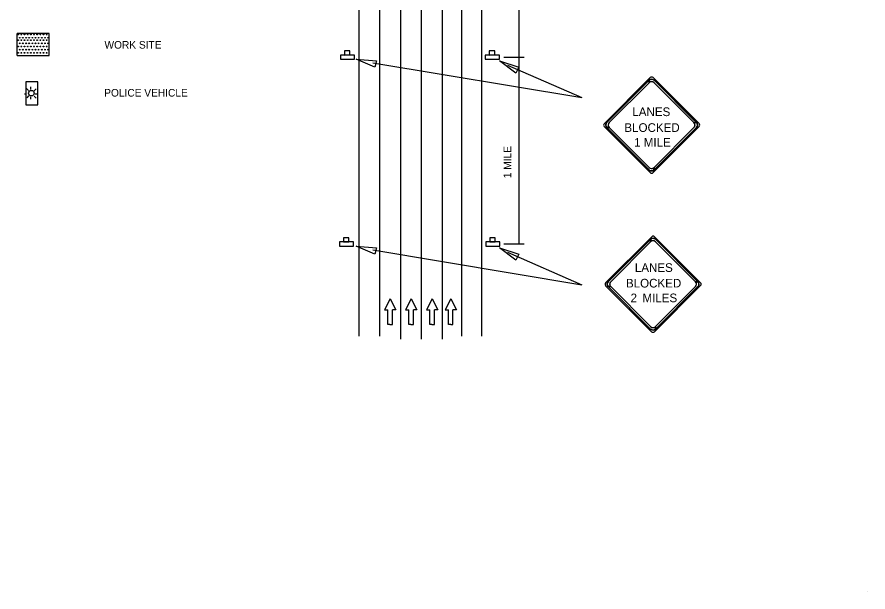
# Model space of a CAD drawing. Extents: x 1536.8 to 1543.6, y 1529.9 to 1539.9.
# Drawn here: x 1536.9 to 1543.62, y 1529.94 to 1534.47 of the extents above; entities that cross this region are included whole.
import ezdxf

# ---------------------------------------------------------------- set-up
doc = ezdxf.new("R2010")
doc.units = 0
for name, color, linetype in [('DETL-DIMS', 7, 'Continuous'), ('DETL-LINE', 7, 'Continuous'), ('DETL-NOTE', 7, 'Continuous'), ('TTLB-TEXT', 7, 'Continuous'), ('USER-BORD', 7, 'Continuous')]:
    doc.layers.add(name, color=color, linetype=linetype)

# ---------------------------------------------------------------- blocks, each defined once
blk = doc.blocks.new('DIR2')
at = {"layer": 'USER-BORD'}
for p, q in [((0, 0.0012), (-0.0342, -0.0477)), ((0, 0.0012), (0.0342, -0.0477)), ((-0.0342, -0.0477), (-0.0132, -0.0477)), ((-0.0132, -0.1133), (-0.0132, -0.0477)), ((0.0342, -0.0477), (0.0132, -0.0477)), ((0.0132, -0.1133), (0.0132, -0.0477)), ((-0.0011, -0.1133), (-0.0132, -0.1133)), ((-0.0011, -0.1133), (0.0011, -0.1133)), ((0.0011, -0.1133), (0.0132, -0.1133))]:
    blk.add_line(p, q, dxfattribs=at)
blk = doc.blocks.new('SIGN13')
at = {"layer": 'USER-BORD'}
for points in [[(-0.0314, 0.0182), (-0.0314, 0), (0.032, 0), (0.032, 0.0182)], [(-0.0134, 0.0182), (0.011, 0.0189), (0.011, 0.0371), (-0.0134, 0.0371)]]:
    blk.add_lwpolyline(points, close=True, dxfattribs=at)

msp = doc.modelspace()

# ---------------------------------------------------------------- linework, layer by layer
at = {"layer": 'DETL-DIMS'}
for p, q in [((1540.8663, 1532.683), (1540.8663, 1537.8458)), ((1540.7471, 1534.1567), (1540.9067, 1534.1567)), ((1539.7115, 1534.1114), (1541.3619, 1533.8372)), ((1540.7751, 1534.0935), (1541.3619, 1533.8372)), ((1540.7471, 1532.683), (1540.9067, 1532.683)), ((1539.7115, 1532.6354), (1541.3619, 1532.3611)), ((1540.7751, 1532.6175), (1541.3619, 1532.3611))]:
    msp.add_line(p, q, dxfattribs=at)
for points in [[(1539.7401, 1534.1285), (1539.7274, 1534.0775), (1539.5808, 1534.141)], [(1540.8647, 1534.0778), (1540.8401, 1534.0314), (1540.7131, 1534.1283)], [(1539.7401, 1532.6525), (1539.7274, 1532.6015), (1539.5808, 1532.665)], [(1540.8647, 1532.6019), (1540.8401, 1532.5554), (1540.7131, 1532.6523)]]:
    msp.add_lwpolyline(points, close=True, dxfattribs=at)
at = {"layer": 'DETL-LINE'}
for p, q in [((1539.6016, 1537.8471), (1539.6016, 1531.9568)), ((1539.7657, 1537.8471), (1539.7657, 1531.9568)), ((1540.4133, 1537.8471), (1540.4133, 1531.9568)), ((1540.5695, 1537.8471), (1540.5695, 1531.9568)), ((1539.9299, 1537.8213), (1539.9299, 1531.9311)), ((1540.0941, 1537.8213), (1540.0941, 1531.9311)), ((1540.2582, 1537.8213), (1540.2582, 1531.9311)), ((1537.1566, 1534.3438), (1536.9026, 1534.3438)), ((1537.1566, 1534.3438), (1536.9026, 1534.3438)), ((1537.1566, 1534.3438), (1536.9026, 1534.3438)), ((1537.1566, 1534.3438), (1536.9026, 1534.3438)), ((1536.9026, 1534.1697), (1536.9026, 1534.3437)), ((1536.9026, 1534.1698), (1536.9026, 1534.3437)), ((1536.9112, 1534.3349), (1536.9112, 1534.3349)), ((1536.912, 1534.3349), (1536.912, 1534.3349)), ((1536.9368, 1534.3349), (1536.9368, 1534.3349)), ((1536.9368, 1534.3349), (1536.9368, 1534.3349)), ((1536.9616, 1534.3349), (1536.9616, 1534.3349)), ((1536.9624, 1534.3349), (1536.9624, 1534.3349)), ((1536.9864, 1534.3349), (1536.9864, 1534.3349)), ((1536.9872, 1534.3349), (1536.9872, 1534.3349)), ((1537.0112, 1534.3349), (1537.0112, 1534.3349)), ((1537.012, 1534.3349), (1537.012, 1534.3349)), ((1537.0368, 1534.3349), (1537.0368, 1534.3349)), ((1537.0368, 1534.3349), (1537.0368, 1534.3349)), ((1537.0616, 1534.3349), (1537.0616, 1534.3349)), ((1537.0616, 1534.3349), (1537.0616, 1534.3349)), ((1537.0864, 1534.3349), (1537.0864, 1534.3349)), ((1537.0872, 1534.3349), (1537.0872, 1534.3349)), ((1537.1112, 1534.3349), (1537.1112, 1534.3349)), ((1537.112, 1534.3349), (1537.112, 1534.3349)), ((1537.1368, 1534.3349), (1537.1368, 1534.3349)), ((1537.1368, 1534.3349), (1537.1368, 1534.3349)), ((1537.1566, 1534.1698), (1537.1566, 1534.3438)), ((1537.1566, 1534.1698), (1537.1566, 1534.3438)), ((1537.1566, 1534.1698), (1537.1566, 1534.3438)), ((1537.1566, 1534.1698), (1537.1566, 1534.3438)), ((1536.9112, 1534.2911), (1536.9112, 1534.2911)), ((1536.912, 1534.2911), (1536.912, 1534.2911)), ((1536.924, 1534.3101), (1536.924, 1534.3101)), ((1536.924, 1534.3101), (1536.924, 1534.3101)), ((1536.924, 1534.2655), (1536.924, 1534.2655)), ((1536.9368, 1534.2911), (1536.9368, 1534.2911)), ((1536.9368, 1534.2911), (1536.9368, 1534.2911)), ((1536.9488, 1534.3101), (1536.9488, 1534.3101)), ((1536.9488, 1534.3101), (1536.9488, 1534.3101)), ((1536.9488, 1534.2655), (1536.9488, 1534.2655)), ((1536.9616, 1534.2911), (1536.9616, 1534.2911)), ((1536.9624, 1534.2911), (1536.9624, 1534.2911)), ((1536.9744, 1534.3101), (1536.9744, 1534.3101)), ((1536.9744, 1534.3101), (1536.9744, 1534.3101)), ((1536.9744, 1534.2655), (1536.9744, 1534.2655)), ((1536.9864, 1534.2911), (1536.9864, 1534.2911)), ((1536.9872, 1534.2911), (1536.9872, 1534.2911)), ((1536.9992, 1534.3101), (1536.9992, 1534.3101)), ((1536.9992, 1534.3101), (1536.9992, 1534.3101)), ((1536.9992, 1534.2655), (1536.9992, 1534.2655)), ((1537.0112, 1534.2911), (1537.0112, 1534.2911)), ((1537.012, 1534.2911), (1537.012, 1534.2911)), ((1537.024, 1534.3101), (1537.024, 1534.3101)), ((1537.024, 1534.3101), (1537.024, 1534.3101)), ((1537.024, 1534.2655), (1537.024, 1534.2655)), ((1537.0368, 1534.2911), (1537.0368, 1534.2911)), ((1537.0368, 1534.2911), (1537.0368, 1534.2911)), ((1537.0488, 1534.3101), (1537.0488, 1534.3101)), ((1537.0488, 1534.3101), (1537.0488, 1534.3101)), ((1537.0488, 1534.2655), (1537.0488, 1534.2655)), ((1537.0616, 1534.2911), (1537.0616, 1534.2911)), ((1537.0616, 1534.2911), (1537.0616, 1534.2911)), ((1537.0736, 1534.3101), (1537.0736, 1534.3101)), ((1537.0736, 1534.3101), (1537.0736, 1534.3101)), ((1537.0736, 1534.2655), (1537.0736, 1534.2655)), ((1537.0864, 1534.2911), (1537.0864, 1534.2911)), ((1537.0872, 1534.2911), (1537.0872, 1534.2911)), ((1537.0992, 1534.3101), (1537.0992, 1534.3101)), ((1537.0992, 1534.3101), (1537.0992, 1534.3101)), ((1537.0992, 1534.2655), (1537.0992, 1534.2655)), ((1537.1112, 1534.2911), (1537.1112, 1534.2911)), ((1537.112, 1534.2911), (1537.112, 1534.2911)), ((1537.124, 1534.3101), (1537.124, 1534.3101)), ((1537.124, 1534.3101), (1537.124, 1534.3101)), ((1537.124, 1534.2655), (1537.124, 1534.2655)), ((1537.1368, 1534.2911), (1537.1368, 1534.2911)), ((1537.1368, 1534.2911), (1537.1368, 1534.2911)), ((1537.1488, 1534.3101), (1537.1488, 1534.3101)), ((1537.1488, 1534.3101), (1537.1488, 1534.3101)), ((1537.1488, 1534.2655), (1537.1488, 1534.2655)), ((1536.9112, 1534.2407), (1536.9112, 1534.2407)), ((1536.912, 1534.2407), (1536.912, 1534.2407)), ((1536.924, 1534.2159), (1536.924, 1534.2159)), ((1536.924, 1534.2159), (1536.924, 1534.2159)), ((1536.9368, 1534.2407), (1536.9368, 1534.2407)), ((1536.9368, 1534.2407), (1536.9368, 1534.2407)), ((1536.9488, 1534.2159), (1536.9488, 1534.2159)), ((1536.9488, 1534.2159), (1536.9488, 1534.2159)), ((1536.9616, 1534.2407), (1536.9616, 1534.2407)), ((1536.9624, 1534.2407), (1536.9624, 1534.2407)), ((1536.9744, 1534.2159), (1536.9744, 1534.2159)), ((1536.9744, 1534.2159), (1536.9744, 1534.2159)), ((1536.9864, 1534.2407), (1536.9864, 1534.2407)), ((1536.9872, 1534.2407), (1536.9872, 1534.2407)), ((1536.9992, 1534.2159), (1536.9992, 1534.2159)), ((1536.9992, 1534.2159), (1536.9992, 1534.2159)), ((1537.0112, 1534.2407), (1537.0112, 1534.2407)), ((1537.012, 1534.2407), (1537.012, 1534.2407)), ((1537.024, 1534.2159), (1537.024, 1534.2159)), ((1537.024, 1534.2159), (1537.024, 1534.2159)), ((1537.0368, 1534.2407), (1537.0368, 1534.2407)), ((1537.0368, 1534.2407), (1537.0368, 1534.2407)), ((1537.0488, 1534.2159), (1537.0488, 1534.2159)), ((1537.0488, 1534.2159), (1537.0488, 1534.2159)), ((1537.0616, 1534.2407), (1537.0616, 1534.2407)), ((1537.0616, 1534.2407), (1537.0616, 1534.2407)), ((1537.0736, 1534.2159), (1537.0736, 1534.2159)), ((1537.0736, 1534.2159), (1537.0736, 1534.2159)), ((1537.0864, 1534.2407), (1537.0864, 1534.2407)), ((1537.0872, 1534.2407), (1537.0872, 1534.2407)), ((1537.0992, 1534.2159), (1537.0992, 1534.2159)), ((1537.0992, 1534.2159), (1537.0992, 1534.2159)), ((1537.1112, 1534.2407), (1537.1112, 1534.2407)), ((1537.112, 1534.2407), (1537.112, 1534.2407)), ((1537.124, 1534.2159), (1537.124, 1534.2159)), ((1537.124, 1534.2159), (1537.124, 1534.2159)), ((1537.1368, 1534.2407), (1537.1368, 1534.2407)), ((1537.1368, 1534.2407), (1537.1368, 1534.2407)), ((1537.1488, 1534.2159), (1537.1488, 1534.2159)), ((1537.1488, 1534.2159), (1537.1488, 1534.2159)), ((1536.9026, 1534.1697), (1537.1566, 1534.1697)), ((1536.9112, 1534.1915), (1536.9112, 1534.1915)), ((1536.912, 1534.1915), (1536.912, 1534.1915)), ((1536.9368, 1534.1915), (1536.9368, 1534.1915)), ((1536.9368, 1534.1915), (1536.9368, 1534.1915)), ((1536.9616, 1534.1915), (1536.9616, 1534.1915)), ((1536.9624, 1534.1915), (1536.9624, 1534.1915)), ((1536.9864, 1534.1915), (1536.9864, 1534.1915)), ((1536.9872, 1534.1915), (1536.9872, 1534.1915)), ((1537.0112, 1534.1915), (1537.0112, 1534.1915)), ((1537.012, 1534.1915), (1537.012, 1534.1915)), ((1537.0368, 1534.1915), (1537.0368, 1534.1915)), ((1537.0368, 1534.1915), (1537.0368, 1534.1915)), ((1537.0616, 1534.1915), (1537.0616, 1534.1915)), ((1537.0616, 1534.1915), (1537.0616, 1534.1915)), ((1537.0864, 1534.1915), (1537.0864, 1534.1915)), ((1537.0872, 1534.1915), (1537.0872, 1534.1915)), ((1537.1112, 1534.1915), (1537.1112, 1534.1915)), ((1537.112, 1534.1915), (1537.112, 1534.1915)), ((1537.1368, 1534.1915), (1537.1368, 1534.1915)), ((1537.1368, 1534.1915), (1537.1368, 1534.1915)), ((1541.9027, 1533.9954), (1541.5386, 1533.6314)), ((1542.2884, 1533.6322), (1541.9252, 1533.9954)), ((1536.971, 1533.9614), (1536.971, 1533.781)), ((1537.0662, 1533.9614), (1536.971, 1533.9614)), ((1537.0662, 1533.781), (1537.0662, 1533.9614)), ((1541.5591, 1533.6399), (1541.8938, 1533.9747)), ((1541.8938, 1533.9554), (1541.5783, 1533.64)), ((1542.2478, 1533.6399), (1541.9324, 1533.9554)), ((1541.9325, 1533.9747), (1542.2671, 1533.6399)), ((1536.9608, 1533.8676), (1536.9764, 1533.8676)), ((1536.9937, 1533.8927), (1536.9786, 1533.9087)), ((1537.0115, 1533.9028), (1537.0115, 1533.9224)), ((1537.0378, 1533.8916), (1537.0528, 1533.9062)), ((1537.0466, 1533.8676), (1537.0622, 1533.8676)), ((1536.9817, 1533.8361), (1536.9968, 1533.8506)), ((1537.0115, 1533.8247), (1537.0115, 1533.8442)), ((1537.0532, 1533.8336), (1537.0383, 1533.8496)), ((1536.971, 1533.781), (1537.0662, 1533.781)), ((1541.5386, 1533.6089), (1541.9018, 1533.2457)), ((1541.8938, 1533.2666), (1541.5591, 1533.6013)), ((1541.5783, 1533.6013), (1541.8938, 1533.2859)), ((1541.9244, 1533.2457), (1542.2884, 1533.6097)), ((1542.2671, 1533.6013), (1541.9325, 1533.2666)), ((1541.9325, 1533.2859), (1542.2478, 1533.6013)), ((1541.9142, 1532.7404), (1541.5502, 1532.3764)), ((1541.5707, 1532.3849), (1541.9054, 1532.7197)), ((1542.3, 1532.3772), (1541.9368, 1532.7404)), ((1541.944, 1532.7197), (1542.2787, 1532.3849)), ((1541.9054, 1532.7004), (1541.5899, 1532.385)), ((1542.2594, 1532.3849), (1541.944, 1532.7004)), ((1541.5502, 1532.3539), (1541.9134, 1531.9907)), ((1541.9054, 1532.0116), (1541.5707, 1532.3463)), ((1541.5899, 1532.3463), (1541.9054, 1532.0309)), ((1541.9359, 1531.9907), (1542.3, 1532.3547)), ((1542.2787, 1532.3463), (1541.944, 1532.0116)), ((1541.944, 1532.0309), (1542.2594, 1532.3463))]:
    msp.add_line(p, q, dxfattribs=at)
for points in [[(1539.9299, 1534.4713), (1539.9299, 1534.3713)], [(1540.0941, 1534.4713), (1540.0941, 1534.3713)], [(1540.2582, 1534.4713), (1540.2582, 1534.3713)], [(1539.9299, 1534.0713), (1539.9299, 1533.9713)], [(1540.0941, 1534.0713), (1540.0941, 1533.9713)], [(1540.2582, 1534.0713), (1540.2582, 1533.9713)], [(1539.9299, 1533.6713), (1539.9299, 1533.5713)], [(1540.0941, 1533.6713), (1540.0941, 1533.5713)], [(1540.2582, 1533.6713), (1540.2582, 1533.5713)], [(1539.9299, 1533.2713), (1539.9299, 1533.1713)], [(1540.0941, 1533.2713), (1540.0941, 1533.1713)], [(1540.2582, 1533.2713), (1540.2582, 1533.1713)], [(1539.9299, 1532.8713), (1539.9299, 1532.7713)], [(1540.0941, 1532.8713), (1540.0941, 1532.7713)], [(1540.2582, 1532.8713), (1540.2582, 1532.7713)], [(1539.9299, 1532.4713), (1539.9299, 1532.3713)], [(1540.0941, 1532.4713), (1540.0941, 1532.3713)], [(1540.2582, 1532.4713), (1540.2582, 1532.3713)], [(1539.9299, 1532.0713), (1539.9299, 1531.9713)], [(1540.0941, 1532.0713), (1540.0941, 1531.9713)], [(1540.2582, 1532.0713), (1540.2582, 1531.9713)]]:
    msp.add_lwpolyline(points, dxfattribs=at)
for points in [[(1541.5591, 1533.6399), (1541.8842, 1533.965), (1541.895, 1533.9758), (1541.8938, 1533.9554), (1541.5783, 1533.64), (1541.5733, 1533.6332), (1541.5704, 1533.6231), (1541.5712, 1533.6138), (1541.5738, 1533.6074), (1541.5783, 1533.6013), (1541.5591, 1533.6013), (1541.5536, 1533.6092), (1541.5511, 1533.6196), (1541.5519, 1533.6274), (1541.5543, 1533.6336)], [(1541.9324, 1533.9746), (1542.2574, 1533.6496), (1542.2682, 1533.6387), (1542.2478, 1533.6399), (1541.9325, 1533.9554), (1541.9256, 1533.9604), (1541.9155, 1533.9632), (1541.9062, 1533.9625), (1541.8999, 1533.96), (1541.8938, 1533.9554), (1541.8938, 1533.9746), (1541.9016, 1533.9801), (1541.9121, 1533.9826), (1541.9198, 1533.9818), (1541.9261, 1533.9794)], [(1541.8938, 1533.2666), (1541.5687, 1533.5917), (1541.5579, 1533.6025), (1541.5783, 1533.6013), (1541.8937, 1533.2859), (1541.9006, 1533.2809), (1541.9107, 1533.278), (1541.9199, 1533.2788), (1541.9263, 1533.2813), (1541.9324, 1533.2859), (1541.9324, 1533.2666), (1541.9245, 1533.2611), (1541.9141, 1533.2586), (1541.9063, 1533.2595), (1541.9, 1533.2619)], [(1542.2671, 1533.6013), (1541.942, 1533.2763), (1541.9311, 1533.2655), (1541.9324, 1533.2859), (1542.2478, 1533.6013), (1542.2528, 1533.6082), (1542.2557, 1533.6182), (1542.2549, 1533.6275), (1542.2524, 1533.6339), (1542.2478, 1533.6399), (1542.2671, 1533.6399), (1542.2726, 1533.6321), (1542.2751, 1533.6216), (1542.2743, 1533.6139), (1542.2718, 1533.6076)], [(1541.5707, 1532.3849), (1541.8957, 1532.71), (1541.9066, 1532.7208), (1541.9054, 1532.7004), (1541.5899, 1532.385), (1541.5849, 1532.3781), (1541.582, 1532.3681), (1541.5828, 1532.3588), (1541.5853, 1532.3524), (1541.5899, 1532.3463), (1541.5707, 1532.3463), (1541.5651, 1532.3542), (1541.5626, 1532.3646), (1541.5635, 1532.3724), (1541.5659, 1532.3786)], [(1541.944, 1532.7196), (1542.269, 1532.3945), (1542.2798, 1532.3837), (1542.2594, 1532.3849), (1541.944, 1532.7004), (1541.9371, 1532.7054), (1541.9271, 1532.7082), (1541.9178, 1532.7075), (1541.9114, 1532.705), (1541.9054, 1532.7004), (1541.9054, 1532.7196), (1541.9132, 1532.7251), (1541.9237, 1532.7276), (1541.9314, 1532.7268), (1541.9377, 1532.7243)], [(1542.2786, 1532.3463), (1541.9535, 1532.0213), (1541.9427, 1532.0105), (1541.944, 1532.0309), (1542.2594, 1532.3463), (1542.2644, 1532.3531), (1542.2673, 1532.3632), (1542.2665, 1532.3725), (1542.264, 1532.3788), (1542.2594, 1532.3849), (1542.2786, 1532.3849), (1542.2841, 1532.3771), (1542.2867, 1532.3666), (1542.2858, 1532.3589), (1542.2834, 1532.3526)], [(1541.9054, 1532.0116), (1541.5803, 1532.3367), (1541.5695, 1532.3475), (1541.5899, 1532.3463), (1541.9053, 1532.0309), (1541.9121, 1532.0259), (1541.9222, 1532.023), (1541.9315, 1532.0238), (1541.9379, 1532.0263), (1541.944, 1532.0309), (1541.944, 1532.0116), (1541.9361, 1532.0061), (1541.9256, 1532.0036), (1541.9179, 1532.0044), (1541.9116, 1532.0069)]]:
    msp.add_lwpolyline(points, close=True, dxfattribs=at)
for centre, radius in [((1536.9119, 1534.3348), 0.00291), ((1536.9367, 1534.3348), 0.00291), ((1536.9623, 1534.3348), 0.00291), ((1536.9871, 1534.3348), 0.00291), ((1537.0119, 1534.3348), 0.00291), ((1537.0367, 1534.3348), 0.00291), ((1537.0615, 1534.3348), 0.00291), ((1537.0871, 1534.3348), 0.00291), ((1537.1119, 1534.3348), 0.00291), ((1537.1367, 1534.3348), 0.00291), ((1536.9119, 1534.2911), 0.00291), ((1536.9239, 1534.31), 0.00291), ((1536.9239, 1534.2655), 0.00291), ((1536.9367, 1534.2911), 0.00291), ((1536.9487, 1534.31), 0.00291), ((1536.9487, 1534.2655), 0.00291), ((1536.9623, 1534.2911), 0.00291), ((1536.9743, 1534.31), 0.00291), ((1536.9743, 1534.2655), 0.00291), ((1536.9871, 1534.2911), 0.00291), ((1536.9991, 1534.31), 0.00291), ((1536.9991, 1534.2655), 0.00291), ((1537.0119, 1534.2911), 0.00291), ((1537.0239, 1534.31), 0.00291), ((1537.0239, 1534.2655), 0.00291), ((1537.0367, 1534.2911), 0.00291), ((1537.0487, 1534.31), 0.00291), ((1537.0487, 1534.2655), 0.00291), ((1537.0615, 1534.2911), 0.00291), ((1537.0735, 1534.31), 0.00291), ((1537.0735, 1534.2655), 0.00291), ((1537.0871, 1534.2911), 0.00291), ((1537.0991, 1534.31), 0.00291), ((1537.0991, 1534.2655), 0.00291), ((1537.1119, 1534.2911), 0.00291), ((1537.1239, 1534.31), 0.00291), ((1537.1239, 1534.2655), 0.00291), ((1537.1367, 1534.2911), 0.00291), ((1537.1487, 1534.31), 0.00291), ((1537.1487, 1534.2655), 0.00291), ((1536.9119, 1534.2407), 0.00291), ((1536.9119, 1534.1914), 0.00291), ((1536.9239, 1534.2159), 0.00291), ((1536.9367, 1534.2407), 0.00291), ((1536.9367, 1534.1914), 0.00291), ((1536.9487, 1534.2159), 0.00291), ((1536.9623, 1534.2407), 0.00291), ((1536.9623, 1534.1914), 0.00291), ((1536.9743, 1534.2159), 0.00291), ((1536.9871, 1534.2407), 0.00291), ((1536.9871, 1534.1914), 0.00291), ((1536.9991, 1534.2159), 0.00291), ((1537.0119, 1534.2407), 0.00291), ((1537.0119, 1534.1914), 0.00291), ((1537.0239, 1534.2159), 0.00291), ((1537.0367, 1534.2407), 0.00291), ((1537.0367, 1534.1914), 0.00291), ((1537.0487, 1534.2159), 0.00291), ((1537.0615, 1534.2407), 0.00291), ((1537.0615, 1534.1914), 0.00291), ((1537.0735, 1534.2159), 0.00291), ((1537.0871, 1534.2407), 0.00291), ((1537.0871, 1534.1914), 0.00291), ((1537.0991, 1534.2159), 0.00291), ((1537.1119, 1534.2407), 0.00291), ((1537.1119, 1534.1914), 0.00291), ((1537.1239, 1534.2159), 0.00291), ((1537.1367, 1534.2407), 0.00291), ((1537.1367, 1534.1914), 0.00291), ((1537.1487, 1534.2159), 0.00291), ((1537.0163, 1533.8724), 0.0221)]:
    msp.add_circle(centre, radius, dxfattribs=at)
for centre, radius, start, end in [((1541.9139, 1533.9842), 0.0159, 45, 135), ((1541.9131, 1533.9554), 0.0273, 45, 135), ((1541.9131, 1533.9361), 0.0273, 45, 135), ((1541.5499, 1533.6202), 0.0159, 135, 225), ((1541.5784, 1533.6206), 0.0273, 135, 225), ((1541.5977, 1533.6207), 0.0273, 135, 225), ((1542.2285, 1533.6206), 0.0273, 315, 45), ((1542.2479, 1533.6206), 0.0273, 315, 45), ((1542.2771, 1533.621), 0.0159, 315, 45), ((1541.9131, 1533.3052), 0.0273, 225, 315), ((1541.9131, 1533.2859), 0.0273, 225, 315), ((1541.9131, 1533.257), 0.0159, 225, 315), ((1541.9247, 1532.7004), 0.0273, 45, 135), ((1541.9255, 1532.7292), 0.0159, 45, 135), ((1541.9246, 1532.6811), 0.0273, 45, 135), ((1541.5899, 1532.3656), 0.0273, 135, 225), ((1541.6092, 1532.3656), 0.0273, 135, 225), ((1542.2401, 1532.3656), 0.0273, 315, 45), ((1542.2594, 1532.3656), 0.0273, 315, 45), ((1541.5615, 1532.3652), 0.0159, 135, 225), ((1542.2887, 1532.366), 0.0159, 315, 45), ((1541.9247, 1532.0502), 0.0273, 225, 315), ((1541.9247, 1532.0309), 0.0273, 225, 315), ((1541.9247, 1532.0019), 0.0159, 225, 315)]:
    msp.add_arc(centre, radius, start, end, dxfattribs=at)
at = {"layer": 'TTLB-TEXT'}
msp.add_line((1543.6215, 1529.9375), (1543.6215, 1529.9375), dxfattribs=at)

# ---------------------------------------------------------------- block references
at = {"layer": 'DETL-LINE'}
for name, p, xscale, yscale in [('SIGN13', (1539.5112, 1534.1411), 1.7510019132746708, 1.751001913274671), ('SIGN13', (1540.6552, 1534.1411), 1.7510019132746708, 1.751001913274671), ('SIGN13', (1539.504, 1532.6668), 1.7510019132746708, 1.751001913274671), ('SIGN13', (1540.6597, 1532.6668), 1.7510019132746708, 1.751001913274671), ('DIR2', (1539.8487, 1532.2468), 1.3132514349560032, 1.7510019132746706), ('DIR2', (1540.0146, 1532.2468), 1.3132514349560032, 1.7510019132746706), ('DIR2', (1540.1805, 1532.2468), 1.3132514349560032, 1.7510019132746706)]:
    msp.add_blockref(name, p, dxfattribs=dict(at, xscale=xscale, yscale=yscale))
at = {"layer": 'DETL-LINE', "xscale": 1.3132514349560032, "yscale": -1.7510019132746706, "rotation": 180}
msp.add_blockref('DIR2', (1540.3268, 1532.2468), dxfattribs=at)

# ---------------------------------------------------------------- texts
at = {"layer": 'DETL-LINE'}
for s, height, p in [('LANES', 0.06829, (1541.7611, 1533.6918)), ('BLOCKED', 0.06829, (1541.6982, 1533.5671)), ('1 MILE', 0.06829, (1541.7752, 1533.45)), ('LANES', 0.06829, (1541.7809, 1532.4624)), ('BLOCKED', 0.06829, (1541.7107, 1532.3395)), ('2', 0.0683, (1541.7471, 1532.2231)), ('MILES', 0.06829, (1541.841, 1532.2234))]:
    msp.add_text(s, height=height, dxfattribs=at).set_placement(p)
at = {"layer": 'DETL-NOTE'}
for s, p in [('WORK SITE', (1537.5932, 1534.2239)), ('POLICE VEHICLE', (1537.591, 1533.8457))]:
    msp.add_text(s, height=0.06, dxfattribs=at).set_placement(p)
msp.add_text('1 MILE', height=0.06, rotation=90, dxfattribs=at).set_placement((1540.8044, 1533.2012))

doc.saveas('drawing.dxf')
